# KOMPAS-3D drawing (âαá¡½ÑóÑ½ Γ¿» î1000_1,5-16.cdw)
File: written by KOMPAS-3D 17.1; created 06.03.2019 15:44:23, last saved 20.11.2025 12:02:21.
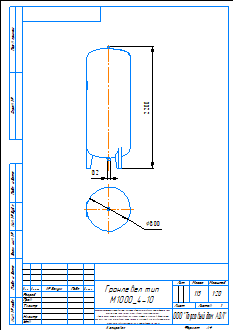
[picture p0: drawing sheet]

Sheet 1: A4, portrait

Title block, sheet 1: name: Гранлевел тип / М1000_4-10; mass: 115; sheets: 1; sheet format: A4; stored path: C:\Users\kka\KOMPAS_Work\!Trash\ГРАНЛЕВЕЛ тип А Расширительный бак\KOMPAS 2D\Гранлевел тип А100_1,5-16.cdw

Views: Проекционный вид 3, Проекционный вид 4
Referenced files in C:\Users\mipv\Desktop\Тип А\SAT\: Гранлевел тип А1000_4-10_1.a3d
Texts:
  kka
  adl
  Гранлевел тип А1000_4-10
  Рама для чертежей
  Лит-Масса-Масштаб
  Материал-Предприятие
  Масштаб
  Изм.
  Лист
  № докум.
  Подп.
  Дата
  Лит.
  Разраб.
  Пров.
  Т.контр.
  Листов
  Внимание! Данный продукт является объектом авторского права ООО «Торговый Дом АДЛ».
  Запрещается изменение, копирование, распространение
  (в том числе путем копирования на другие сайты и ресурсы в Интернете)
  или любое иное использование информации и объектов без предварительного
  согласия правообладателя (ООО «Торговый Дом АДЛ»).
  Н.контр.
  Утв.
  ООО "Торговый дом АДЛ"
  Изменение
  Номер документа
  Подпись
  Обозначение документа
  Наименование изделия
  Масса изделия по ГОСТ 2.109-73
  Порядковый номер листа
  Общее количество листов в документе
  Характер работы, выполненной лицом, подписавшим документ
  Наименование или индекс предприятия, выпускающего документ
  Инв. № подл.
  Подп. и дата
  Взам. инв. №
  Инв. № дубл.
  Инвентарный номер подлинника по ГОСТ 2.501-68
  Подпись принявшего подлинник в отдел технической документации
  Инвентарный номер подлинника, взамен которого выпущен данный подлинник
  Инвентарный номер дубликата по ГОСТ 2.502-68
  Подпись принявшего дубликат в отдел технической документации
  Справ. №
  Перв. примен.
  Обозначение документа, взамен или на основании которого выпущен данный документ
  Обозначение документа, в котором впервые записан данный документ
  Подпись лица, копировавшего чертеж
  Обозначение формата листа
  !Рама для чертежа
Dimensions and other numbers on the sheet: 2200; 800; 1:20; 1; 115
